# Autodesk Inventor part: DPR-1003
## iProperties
Created: 2004-11
Part Number: DPR-1003
Cost Center: 0 lbmass
Document SubType Name: Modeling
Designer: busseym
Manufacturer: Standard
Standards Organization: Custom
Stock Number: DPR-1003
Density: 1 g/cm^3
CAGE: 1LJX3
Dept. ID: Product Design
Description #2: ---
Finish #1: ---
Finish #2: ---
Material ID: ---
Project Number: ---
Author: busseym
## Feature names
1. Revolution1
2. Extrusion1
3. Extrusion2
4. Extrusion3
5. Fillet1
6. Fillet2
7. Extrusion4
8. Mirror1
9. Mirror2
